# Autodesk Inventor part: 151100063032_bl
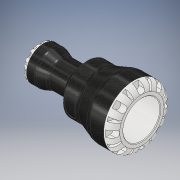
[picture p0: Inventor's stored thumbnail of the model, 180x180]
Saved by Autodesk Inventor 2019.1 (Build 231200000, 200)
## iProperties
Created: 2016-12
Part Number: 151100063032_bl
Material: PVC-Piping
Description: PLASSON G-PLASS  REDUCING COUPLING  63 x 32
Document SubType Name: Modeling
Designer: KIM
Mass: 309.689 g
Surface Area: 488.063 cm^2
Volume: 221.206 cm^3
Density: 1.4 g/cm^3
Appearance: Black Cast
Author: KIM
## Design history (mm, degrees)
derived "151100.ipt"
feature "Solid1::151100.ipt" dims "ScaleForDerivedMember" = 10
tag "TaggingFeature1"
body "Solid1"
other parameters: "d_" = 63 [user parameter], "d1" = 32 [user parameter], "E_" = 103 [user parameter], "H_" = 177 [user parameter], "l_" = 96 [user parameter], "E1" = 58 [user parameter], "l1" = 57 [user parameter], "Plasson" = 1 [user parameter], "d20" = 9 [user parameter], "d21" = 13.7 [user parameter], "d23" = 103 [user parameter], "d24" = 75.6 [user parameter], "d40" = 58 [user parameter], "d59" = 20.4117 [user parameter], "d0" = 177 [user parameter], "d2" = 40.32 [user parameter], "d3" = 63 [user parameter], "d4" = 103 [user parameter], "d5" = 75.6 [user parameter], "d6" = 96 [user parameter], "d7" = 5.25 [user parameter], "d8" = 58 [user parameter], "d9" = 32 [user parameter], "d11" = 23.94 [user parameter], "d12" = 57 [user parameter], "d13" = 2.66667 [user parameter], "d14" = 82.4 [user parameter], "d15" = 46.4 [user parameter], "d16" = 20 deg [user parameter], "d17" = 20 deg [user parameter], "d18" = 130 deg [user parameter], "d22" = 10.96 [user parameter], "d25" = 10.96 [user parameter], "d26" = 0 [user parameter], "d28" = 360 deg [user parameter], "d30" = 8 deg [user parameter], "d31" = 1.26 [user parameter], "d32" = 8 deg [user parameter], "d33" = 1.26 [user parameter], "d35" = 0 [user parameter], "d37" = 360 deg [user parameter], "d39" = 7.2 [user parameter], "d42" = 7.2 [user parameter], "d43" = 0 [user parameter], "d45" = 360 deg [user parameter], "d47" = 0.64 [user parameter], "d48" = 8 deg [user parameter], "d49" = 8 deg [user parameter], "d50" = 0.64 [user parameter], "d52" = 0 [user parameter], "d54" = 360 deg [user parameter], "d56" = 11.6 [user parameter], "d57" = 20.6 [user parameter], "d58" = 0.5 [user parameter], "d60" = 12.36 [user parameter], "d61" = 15.75 [user parameter], "d62" = 17.46 [user parameter], "d63" = 0 [user parameter], "d66" = 0 [user parameter], "d68" = 360 deg [user parameter], "d75" = 10.20585 [user parameter], "d77" = 80.34 [user parameter], "d78" = 1.03 [user parameter]
